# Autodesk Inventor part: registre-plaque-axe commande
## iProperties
Author: chr
Created: 2001-06
Part Number: registre-plaque-axe commande
Material: Par défaut
Document SubType Name: Modélisation
Designer: chr
Control State: 0
Master: False
Checked Out: False
PropertySet Name: Design Tracking Control
Shininess: 21.0
PropertySet Name: _Private Model Information
Length Units: 11269
Angle Units: 11286
Time Units: 11279
Mass Units: 11290
Length Display Precision: 3
Angle Display Precision: 2
Compacted: False
Density: 0.0
Volumn: 0.0
Area: 0.0
PropertySet Name: Model Information
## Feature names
1. Extrusion1
2. Extrusion2
